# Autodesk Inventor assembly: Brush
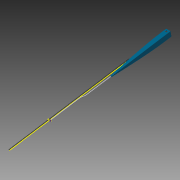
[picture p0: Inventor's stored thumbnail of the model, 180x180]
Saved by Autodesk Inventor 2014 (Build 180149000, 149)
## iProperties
Created: 2006-04
Part Number: Brush
Document SubType Name: Assembly
Designer: Autodesk, Inc.
Mass: 143.512 g
Surface Area: 423.543 cm^2
Volume: 24.3841 cm^3
Density: 5.88547 g/cm^3
Author: Autodesk, Inc.
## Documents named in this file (4)
- C:\Users\iTools\Desktop\tutorial files\Dynamic Simulation 4\Components\Brush.iam
- C:\Users\iTools\Desktop\tutorial files\Dynamic Simulation 4\Components\Arm.ipt
- C:\Users\iTools\Desktop\tutorial files\Dynamic Simulation 4\Components\Wiper.ipt
- C:\Users\iTools\Desktop\tutorial files\Dynamic Simulation 4\Components\Brush.ipt
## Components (3 placed, 3 different names)
1. Arm:1
2. Wiper:1
3. Brush:1
